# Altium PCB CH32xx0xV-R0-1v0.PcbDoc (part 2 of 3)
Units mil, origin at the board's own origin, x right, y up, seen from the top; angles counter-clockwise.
Board outline 3661.42 x 3267.72 mil, 2 copper layers (Top Layer, Bottom Layer); 68 components, 119 nets, 417 pads, 746 vias.
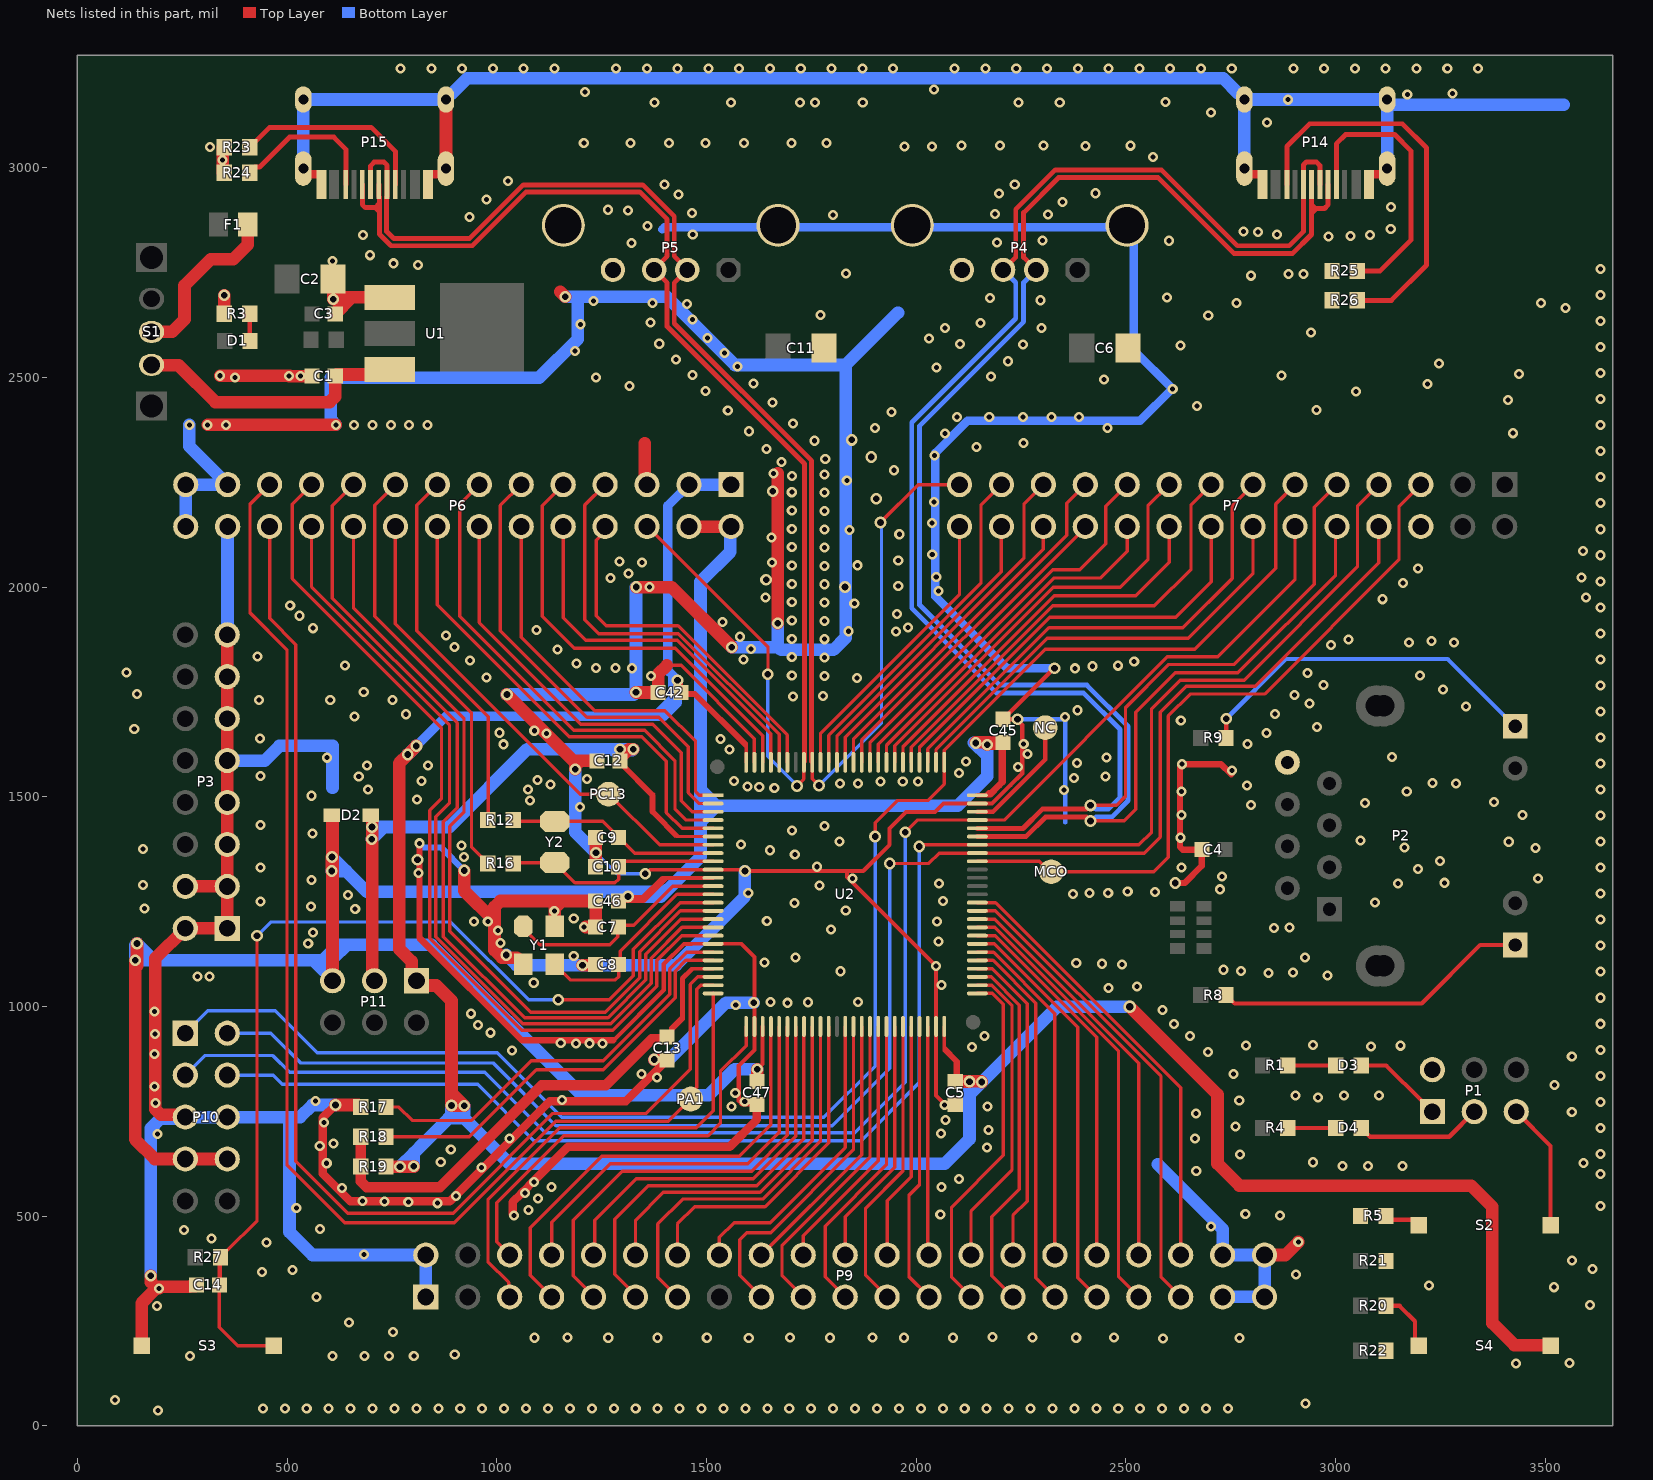
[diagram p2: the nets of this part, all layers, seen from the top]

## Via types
v1: diameter 24, hole 12, Top Layer to Bottom Layer, tented both sides, 648 vias
v2: diameter 28, hole 16, Top Layer to Bottom Layer, tented both sides, 97 vias
v3: diameter 30, hole 18, Top Layer to Bottom Layer, tented both sides, 1 vias

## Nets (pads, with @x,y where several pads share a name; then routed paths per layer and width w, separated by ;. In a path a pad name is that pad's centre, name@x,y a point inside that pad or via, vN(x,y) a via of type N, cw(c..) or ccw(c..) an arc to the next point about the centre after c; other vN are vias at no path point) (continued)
GND: C1.2 C2.2 C3.2 C4.1 C5.2 C6.2 C7.1 C8.1 C9.1 C10.1 C11.2 C12.1 C13.2 C14.1 C42.1 C45.2 C46.2 C47.1 P1.2 P2.8 P3.1 P3.2 P3.3 P3.4 P3.5 P3.7 P3.9 P3.11 P3.13 P3.15 P4.0 P4.4 P5.0 P5.4 P6.5 P6.25 P6.26 P6.27 P6.28 P7.6 P9.1 P9.2 P9.39 P9.40 P9.41 P9.42 P10.5 P10.6 P14.0 P14.A1 P14.B1 P15.0 P15.A1 P15.B1 R3.2 R5.1 R17.1 R21.2 R22.2 R23.2 R24.2 R25.2 R26.2 S3.1 U1.1 U2.10 U2.19 U2.27 U2.49 U2.74 U2.99 Y1.2 Y1.4 | length 26517
  Top Layer w8: 1364.22,1326.45 U2.10@1515.75,1326.45 1515.94,1326.26 v2@1588.24,1326.26 ; 1405.24,1813.28 1439.47,1813.28 1614.17,1638.58 U2.99@1614.17,1582.36 ; 1464.71,1149.29 U2.19@1515.75,1149.29 1583.24,1149.29
  Top Layer w10: C2.2@609.71,2734.59 611.56,2732.74 C2.2@611.56,2709.67 ; C2.2@612.21,2756.59 C2.2@614.72,2754.08 ; C3.2@614.72,2651.67 C2.2@614.72,2701.58 ; 1277.95,919.19 1398.11,1039.35 1398.11,1101.2 1446.2,1149.29 1464.71,1149.29 ; 1583.24,1149.29 1614.17,1118.36 U2.27@1614.17,952.44 1614.17,896.1 1577.04,858.97 1577.04,774.62 1585.29,766.37 C47.1@1620.21,766.37 ; v2@1588.24,1326.26 v2(1591.64,1322.86) 1834.86,1322.86 ; C5.2@2093.21,766.36 2068.86,766.36 2047.24,787.97 U2.49@2047.24,952.44 v1(2047.24,1096.4) 1834.86,1308.78 1834.86,1322.86 ; v2(2329.66,1806.6) 2328.94,1806.6 C45.2@2207.3,1684.96 v2(2241.77,1684.96) 2241.77,1682.65 2252.86,1671.56 2252.86,1637.45 2253.73,1636.57 2253.73,1626.93 2252.86,1626.05 2253.73,1625.18 2253.73,1615.53 2252.86,1614.66 2252.86,1555.73 2224.09,1526.97 2181.06,1483.93 U2.74@2145.67,1483.93 2064.97,1483.93 2045,1463.95 1975.96,1463.95 1936.47,1424.46 1936.47,1385.48 1873.85,1322.86 1834.86,1322.86
  Top Layer w15: v1@815.67,1379.21 815.67,1163.41 1059.89,919.19 1277.95,919.19 ; v2(2617.76,1294.49) 2640.39,1294.49 2681.03,1335.14 C4.1@2681.03,1374.02 ; v1@2632.22,1577.36 2628.8,1573.94 2628.8,1380.61 2635.39,1374.02 C4.1@2681.03,1374.02 ; v1(2633.76,1577.68) 2633.87,1577.79 2726.78,1577.79 v1@2751.11,1553.47 ; C4.1@2681.03,1374.36 C4.1@2681.03,1374.02
  Top Layer w20: P15.0@538.56,2998.15 538.56,2993.36 547.51,2984.41 579.86,2984.41 581.67,2982.6 P15.B1@581.67,2959.96 ; v2(615.18,765.16) 584.7,734.68 584.7,601.62 650.86,535.45 887.67,535.45 1126.57,774.35 1307.98,774.35 C13.2@1406.03,872.4 ; P15.A1@835.61,2959.96 835.61,2982.6 837.42,2984.41 869.77,2984.41 878.72,2993.36 P15.0@878.72,2998.15 ; v1@1039.94,502.38 1039.94,503.15 1037.84,505.26 1037.84,533.65 1058.53,554.34 1065.69,554.34 1066.23,554.88 v1@1066.23,556.42 ; v1@1063.41,559.23 v1@1087.61,583.43 ; v1@1087.74,583.3 1089.27,583.3 1089.81,583.84 1089.81,585.62 1169.81,665.63 1555.42,665.63 1620.21,730.42 C47.1@1620.21,766.37 ; P14.0@2782.7,2998.15 2782.7,2993.36 2791.64,2984.41 2824,2984.41 2825.81,2982.6 P14.B1@2825.81,2959.96 ; P14.A1@3079.74,2959.96 3079.74,2982.6 3081.56,2984.41 3113.91,2984.41 3122.85,2993.36 P14.0@3122.85,2998.15
  Top Layer w30: S3.1@153.21,191.36 153.21,292.44 185.42,324.65 v1@185.42,332.06 ; v2(174.88,357.77) 174.88,342.6 v1@185.42,332.06 ; v1(194.6,327.96) 189.52,327.96 v1@185.42,332.06 ; P10.5@257.21,736.36 251.47,742.1 198.44,742.1 185.26,755.28 v1(185.26,934.84) 185.26,1114.41 P3.2@257.21,1186.36 P3.1@357.21,1186.36 P3.3@357.21,1286.36 ; P3.4@257.21,1286.36 P3.3@357.21,1286.36 ; C14.1@283.44,336.36 280.44,333.36 268.56,333.36 267.26,332.06 v1@185.42,332.06 ; v1(310.42,2386.99) v1(354.11,2386.99) v1(616.26,2386.99) ; v1(340.29,2504.04) 505.7,2504.04 v1(504.86,2503.21) v1(532.28,2503.21) C1.2@559.71,2503.21 ; R24.2@346.04,2988 R23.2@346.04,3048.82 ; R3.2@350.14,2651.66 v2(350.14,2696.05) ; P3.15@357.21,1886.36 357.71,1886.36 357.21,1885.86 357.21,1786.86 357.71,1786.36 357.21,1785.86 P3.11@357.21,1686.36 P3.9@357.21,1586.36 P3.7@357.21,1486.36 P3.5@357.21,1386.36 P3.3@357.21,1286.36 ; C2.2@609.71,2734.59 609.05,2733.94 609.05,2712.18 611.56,2709.67 609.96,2708.07 v2(609.96,2686.32) ; C3.2@614.72,2651.67 653.76,2690.71 ; C2.2@614.72,2701.58 625.59,2690.71 U1.1@744.97,2690.71 U1.1@754.97,2690.71 ; v2(615.18,765.16) 670.24,765.16 670.85,764.55 671.84,764.55 675.15,761.24 R17.1@675.15,760.26 ; P15.0@878.72,2998.15 P15.0@878.72,3162.71 ; v2(922.19,1324.13) 922.19,1275.99 994.38,1203.8 ; v2@1011.96,1116.6 994.38,1134.18 994.38,1203.8 ; v2@1015.82,1116.6 1046.96,1116.6 1052.62,1110.95 1056.56,1110.95 1063.21,1104.3 Y1.2@1063.21,1100.36 ; v2(1024.15,1743.93) 1182.39,1585.69 1199.47,1585.69 ; Y1.4@1138.01,1190.91 1138.01,1233.66 1155.83,1251.48 ; 1151.69,2703.86 v2(1163.05,2692.5) ; v2(1186.92,1565.65) 1186.92,1573.14 1199.47,1585.69 ; v2(1204.2,1098.6) 1234.27,1098.6 C8.1@1235.4,1099.73 ; v1@1212.33,1189.52 1234.99,1189.52 C7.1@1235.4,1189.11 C46.2@1235.39,1251.48 1155.83,1251.48 ; C10.1@1235.4,1333.23 C9.1@1235.4,1402.61 ; C12.1@1238.69,1585.69 1199.47,1585.69 ; v2(1331.85,1749.37) 1332.53,1748.68 C42.1@1384.49,1748.68 1384.49,1792.53 1405.24,1813.28 ; v2(1332.61,2000.18) 1416.87,2000.18 v2(1560.42,1856.63) ; 1352.52,2343.09 1352.52,2250.04 P6.5@1358.21,2244.36 ; v2(1375.46,873.41) 1403.46,873.41 1404.24,874.19 C13.2@1406.03,872.4 ; v2(1669.62,1913.93) v1@1669.62,2270.87 ; P9.42@2830.71,407.44 2880.08,407.44 v1(2911.05,438.41) ; 994.38,1203.8 994.38,1237.5 1008.37,1251.48 1155.83,1251.48
  Bottom Layer w8: v2(1236.3,1366.46) 1286.52,1316.25 v2(1354.01,1316.25)
  Bottom Layer w10: v2(2241.77,1684.96) 2355.18,1684.96 2355.18,1438.4
  Bottom Layer w15: v1@815.67,1379.21 867.11,1379.21 v2(922.19,1324.13)
  Bottom Layer w20: 1394.51,2852.66 1399.51,2857.66 2502.7,2857.66 2518.46,2841.9 2518.46,2565.52 v1(2611.69,2472.29) ; v2(2329.66,1806.6) 2216.8,1806.6 2045.84,1977.55 2045.84,2320.25 2122.33,2396.74 2533.85,2396.74 v1@2610.92,2473.81
  Bottom Layer w30: v2(174.88,357.77) 174.88,709.7 197.21,732.03 252.88,732.03 P10.5@257.21,736.36 P10.6@357.21,736.36 505.67,736.36 ; P6.28@258.21,2144.36 P6.27@258.21,2244.36 P6.25@358.21,2244.36 266.34,2336.23 v1@266.34,2386.59 ; P3.9@357.21,1586.36 446.8,1586.36 481.8,1621.36 608.21,1621.36 608.21,1521.36 ; P3.15@357.21,1886.36 357.71,1886.86 357.71,2143.86 P6.26@358.21,2144.36 ; P15.0@538.56,2998.15 P15.0@538.56,3162.71 P15.0@878.72,3162.71 878.72,3171.99 883.05,3176.32 892.32,3176.32 929.72,3213.71 2731.7,3213.71 2769.09,3176.32 2778.37,3176.32 2782.7,3171.99 P14.0@2782.7,3162.71 ; v2(615.18,765.16) 560.03,765.16 531.22,736.36 505.67,736.36 ; v1(616.26,2386.99) 604,2399.24 604,2499.25 1100.67,2499.25 1193.06,2591.65 1193.06,2692.5 ; P9.1@830.71,307.44 P9.2@830.71,407.44 560.54,407.44 505.67,462.31 505.67,736.36 ; v2(1022.37,1122.92) 1046.69,1098.6 v2(1204.2,1098.6) 1427.65,1098.6 1591.64,1262.59 v2(1591.64,1322.86) ; v2(1024.15,1743.93) 1326.41,1743.93 v2(1331.85,1749.37) 1331.85,1999.41 v2(1332.61,2000.18) ; v2(1163.05,2692.5) 1193.06,2692.5 ; v2(1186.92,1565.65) 1186.92,1415.84 v2(1236.3,1366.46) ; v2(1375.46,873.41) 1410.99,873.41 1546.82,1009.23 v2(1612.92,1009.23) ; v2(1560.42,1856.63) 1671.57,1856.63 ; v2(1669.62,1913.93) 1669.62,1858.58 1671.57,1856.63 ; 1956.65,2654.66 1831.65,2529.66 ; 2576.15,623.54 2730.71,468.98 P9.40@2730.71,407.44 P9.42@2830.71,407.44 P9.41@2830.71,307.44 P9.39@2730.71,307.44 ; P14.0@2782.7,2998.15 P14.0@2782.7,3162.71 ; P14.0@3122.85,2998.15 P14.0@3122.85,3154.52 ; 3544.32,3150.19 3127.18,3150.19 P14.0@3122.85,3154.52 ; 1193.06,2692.5 1405.12,2692.5 1567.96,2529.66 1831.65,2529.66 ; 1671.57,1856.63 1677.92,1850.28 1802.63,1850.28 1831.65,1879.31 1831.65,2529.66 ; P14.0@2782.7,3162.71 P14.0@3122.85,3162.71 P14.0@3122.85,3154.52
  other v1: 191.6,36.82 442.13,41.5 494.43,41.5 546.73,41.5 599.03,41.5 651.32,41.5 703.62,41.5 755.92,41.5 808.22,41.5 860.52,41.5 912.82,41.5 965.12,41.5 1017.42,41.5 1069.72,41.5 1122.02,41.5 1174.32,41.5 1226.62,41.5 1278.92,41.5 1331.22,41.5 1383.52,41.5 1435.82,41.5 1488.12,41.5 1540.41,41.5 1592.71,41.5 1645.01,41.5 1697.31,41.5 1749.61,41.5 1801.91,41.5 1854.21,41.5 1906.51,41.5 1958.81,41.5 2011.11,41.5 2063.41,41.5 2115.71,41.5 2168.01,41.5 2220.31,41.5 2272.61,41.5 2324.91,41.5 2377.2,41.5 2429.5,41.5 2481.8,41.5 2534.1,41.5 2586.4,41.5 2638.7,41.5 2691,41.5 2743.3,41.5 2928.04,53.07 89.88,61.94 3429.78,148.85 3557.96,150.13 268.2,166.17 607.92,166.19 684.5,166.19 743.23,166.19 801.96,166.19 899.65,170.11 2588.78,208.08 1600.73,209.45 1089.54,210.13 1265.72,210.13 1383.18,210.13 1500.64,210.13 1699,210.78 1794.28,210.13 1895.54,210.78 1970.47,210.13 2087.93,210.13 2277.32,210.78 2381.57,210.13 2471.19,210.38 2771.38,209.92 1168.06,211.08 2182.38,212.1 752.38,224.25 647.76,246.19 189.7,285.56 3606.24,288.27 569.59,307.27 3520.68,330.63 3223.25,334.54 2905.17,361.29 440.25,367.1 512.58,371.6 3612.17,373.83 3563.88,394.17 683.72,408.85 450.3,437.43 319.53,446.87 253.81,466.97 578.08,469.44 2702.61,475.08 1040.71,501.3 2866.99,501.86 2057.41,503.6 2784.69,505.73 1075.69,514.87 521.78,519.31 3631.78,524.36 858.07,530.93 788.86,534.31 732.37,535.46 679.94,536.29 1098.59,542.55 902.67,548.33 1067.54,555.11 631.09,567.58 1130.56,569.74 2060.52,569.58 1089.04,581.99 2101.61,588.26 3631.78,600.23 2667.79,607.47 963.7,615.95 3016.4,619.76 3077.38,619.76 3159.75,619.76 594.4,626.24 3590.8,626.6 866.3,628.83 2946.2,628.64 2771.99,647.61 3631.78,648.49 890.21,659.37 2169.21,664.16 577.74,667.52 610.31,673.2 1030.74,685.31 2665.22,685.19 190.41,695.82 2059.15,697.65 2172.9,705.71 3631.78,710.55 2761.74,714.23 587.59,723.58 2069.8,729.59 2666.93,744.98 3563.19,748.55 1559.88,761.34 2169.67,761.57 2067.96,765.62 186.55,769.53 3631.78,772.62 1591.16,773.5 567.89,775.08 2770.28,775.73 1155.56,776.94 2957.91,782.59 2904.06,787.34 3103.63,787.34 3020.36,788.18 1568.53,793.49 183.66,809.03 3521.77,812.99 1382.05,830.54 3631.78,834.68 1345.34,839.54 2756.69,839.13 3563.19,880.87 183.74,886.43 2695.7,891.01 1036.03,895.07 3631.78,896.75 2133.52,902.97 3084.41,904.13 2786.56,906.72 3154.31,906.48 2945.84,908.01 1188.43,911.55 1252.38,911.55 1152.46,912.55 1220.65,912.3 2652.95,929.56 2162.45,930.01 985.13,937.47 954.96,955.46 2615.09,958.3 3631.78,958.81 938.61,982.77 183.3,987.76 2587.76,991.24 1569.73,1003.61 1693.2,1008.89 1741.54,1010.11 1652.18,1010.92 1860.98,1011.06 3631.78,1020.88 2458.12,1043.87 2526.14,1048.12 2060.66,1051.18 1088.08,1056.6 286.03,1071.34 314.43,1071.34 2980.38,1074.13 2840.2,1080.37 2898.9,1081.19 3631.78,1082.94 1819.45,1084.05 2774.17,1084.71 2732.3,1087.67 2490.71,1099.85 2443.24,1101.97 2381.6,1103.39 1638.14,1104.81 1712.36,1116.58 2927.41,1116.36 1183.44,1120.75 3631.78,1145 550.31,1150.17 1008.72,1151.66 2053.44,1155.11 561.8,1176.18 1003.1,1181.08 1796.64,1183.62 2853.68,1187 2890.63,1187.87 1207.4,1189.11 945.13,1202.27 2049.83,1202.74 978.44,1203.14 1643.7,1204.1 3631.78,1207.07 1183.44,1210.05 1137.01,1227.48 1831.98,1229.08 662.36,1232.84 159.59,1233.75 557.4,1237.99 1709.93,1246.75 3094.19,1248.26 436.16,1250.21 2063.54,1251.09 645.12,1265.53 2374.19,1268.2 3631.78,1269.13 1599.51,1270.38 2457.87,1270.71 2413.46,1270.94 2569.16,1272.79 2504.4,1274.67 2724.73,1279.51 1769.54,1288.64 156.18,1289.6 2054.16,1293.68 3148.33,1293.79 3259.69,1295.02 558.37,1301.49 1848.36,1305.25 3482.39,1305.28 2729.42,1310.23 812.88,1318.31 3196.69,1328.34 436.16,1331.67 2632.82,1331.21 3631.78,1331.2 1763.45,1333.21 3249.23,1346.7 921.99,1356.03 1710.47,1362.67 1651.74,1372.59 155.91,1375.99 3477.17,1378.33 3164.4,1379.3 915.38,1383.82 1582.01,1386.15 815.67,1389.21 3412.89,1392.84 1817.57,1393.49 3631.78,1393.26 3059.48,1396.25 2630.67,1402.45 560.24,1412.22 1704.04,1419.73 1781.52,1430.7 436.16,1432.49 3631.78,1455.32 3445.86,1456.6 2632.08,1456.87 1198.69,1476.21 2797.87,1480.91 3070.08,1485.27 3377.55,1487.43 1079.51,1490.71 810.12,1493.85 558,1502.57 2633.03,1512.23 3169.7,1512.83 2352.6,1516.24 693.14,1517.5 1074.07,1516.99 3631.78,1517.39 1661.58,1521.45 1625.79,1523.67 1597.73,1524.11 2788.76,1527.04 1128,1529.68 1861.36,1531.23 1818.03,1532.25 3287.33,1531.9 3231.21,1533.2 1914.55,1536.36 1967.9,1536.36 2004.51,1536.36 1565.36,1537.46 819.89,1538.08 1096.73,1540.1 1215.41,1542.81 2376.71,1544.93 670.8,1548.46 2450.88,1548.51 436.16,1549.55 2101.58,1556.49 2752.95,1562.67 2242.32,1571.08 690.69,1574.76 835.83,1574.6 3631.78,1579.45 2383.22,1580.13 2118.89,1584.5 594.92,1593.21 2453.43,1593.58 3134.73,1594.43 2264.98,1602.09 1554.56,1612.67 1015.77,1625.26 2256.41,1626.05 2790.41,1626.37 1533.76,1637.6 434.97,1639.49 3631.78,1641.52 1118.89,1650.59 1006.09,1652.78 2835.75,1652.32 1089.29,1657.55 135.45,1661.76 2955.65,1666.03 2630.88,1681.54 2355.18,1690.68 660.43,1691.46 783.45,1696.86 2855.76,1697.36 3631.78,1703.58 2384.12,1706.38 3311.35,1715.83 2937.33,1722.19 433.34,1730.68 602.82,1730.66 751.08,1731.25 1706.45,1738.7 1777.36,1740.63 2902.45,1742.28 141.54,1745.31 682.7,1750.42 3256.09,1756.29 3631.78,1765.64 2971.02,1767.11 1859.2,1783.64 975.01,1784.57 1367.66,1787.82 1780.94,1788.36 3201.33,1788.86 1703.32,1789.34 2933.19,1794.89 116.64,1796.56 1322.78,1806.58 2379.11,1806.49 1236.04,1807.15 1283.46,1807.15 2420.78,1811.35 2481.46,1812.56 637.73,1813.42 1189.77,1817.56 2519.89,1823.08 936.11,1824.63 1588.44,1827.6 3631.78,1827.71 1780.94,1832.05 1703.32,1833.04 429.43,1835.09 1144.27,1851.74 1605.68,1852.01 898.95,1857.15 2989.59,1861.54 3282.71,1867.52 3175.08,1868.24 3228.53,1871.13 1780.94,1875.74 3030.51,1875.18 1703.32,1876.73 1579.34,1881.7 878.63,1884.44 3631.78,1889.77 1838.68,1894.74 1951.85,1894.55 1094.71,1897.33 561.82,1902 1980.19,1903.96 1537.69,1916.65 1780.94,1919.44 1703.32,1920.42 529.71,1931.7 1954.06,1935.7 3631.78,1951.84 507.38,1956.39 1852.32,1961.15 1780.94,1963.13 1703.32,1964.11 3112.33,1971.12 1640.74,1975.45 3596.78,1974.93 2053.09,1991.2 1363.69,2000.75 1957.17,2002.27 1780.94,2006.82 1703.32,2007.8 3160.54,2009.6 3631.78,2013.9 1270.96,2021.41 2047.84,2023.64 3586.53,2023.19 1314.37,2032.85 3196.58,2044.66 1780.94,2050.51 1703.32,2051.49 1859.85,2052.08 1655.66,2058.22 1345.94,2058.89 1292.27,2061.26 1957.17,2063.87 3631.78,2075.96 2038.27,2077.79 3590.15,2085.93 1780.94,2094.2 1703.32,2095.19 1654.6,2118.22 1959.66,2126.09 1841.14,2135.83 1780.94,2137.89 3631.78,2138.03 1703.32,2138.88 2037.58,2153.23 1780.94,2181.59 1703.32,2182.57 3631.78,2200.09 2042.38,2203.29 1780.94,2225.28 1703.32,2226.26 1834.47,2254.04 3631.78,2262.16 1703.8,2264.95 1780.94,2268.97 1659.87,2270.87 1946.73,2278.68 1679.23,2298.32 1783.16,2305.56 2044.04,2314.11 3631.78,2324.22 1642.91,2329.76 2143.83,2334.55 2255.47,2343.57 1757.61,2349 2068.99,2366.11 3422.65,2366.96 1601,2371.67 1901.4,2378.97 2456.31,2379.13 3631.78,2386.29 266.73,2386.99 659.95,2386.99 703.64,2386.99 747.33,2386.99 791.03,2386.99 834.72,2386.99 1706.5,2389.89 2097.23,2405.76 2174.15,2405.76 2254.35,2405.76 2323.08,2405.76 2387.73,2405.76 1940.79,2417.32 1550.71,2421.26 2954.33,2421.86 2670.05,2431.96 1657.19,2440.37 3411.39,2445.76 3631.78,2448.35 3048.92,2466.02 1497.62,2468.06 1316.73,2479.4 3219.2,2483.99 1611.57,2485.59 2447.46,2494.95 375.87,2499.78 1236.7,2499.87 2178.87,2502.27 2871.5,2504.43 1466.89,2505.78 3437.28,2507.67 3631.78,2510.41 2048,2524.09 1573.45,2526.2 3247.04,2533.56 2218.7,2538.63 1427.54,2543.09 1542.72,2558.44 1186.69,2562.89 3631.78,2572.48 2630.44,2575.94 2254.19,2578.45 2104.1,2579.33 1387.28,2580.32 2030.88,2592.48 1502.7,2594.46 2940.98,2607.32 2069.14,2618.29 2298.34,2618.27 1199.9,2626.74 2153.3,2630.25 1366.94,2631.39 3631.78,2634.54 1466.34,2637.79 1771.55,2648.55 2696.39,2648.02 3548.2,2665.51 1453.28,2675.49 1371.01,2677.04 2763.87,2677.16 3489.38,2677.15 1230.72,2681.78 2296.61,2684.06 2175.74,2689.8 2598.24,2690.96 3631.78,2696.61 2798.27,2742.5 1833.07,2747.49 2887.24,2746.86 2923.15,2747.09 3631.78,2758.67 812.45,2768.2 754.07,2772.2 608.21,2777.59 698.09,2791.39 1320.63,2820.51 2193.07,2821.72 2301.5,2826.65 2602.84,2825.92 2983.58,2836.04 3035.83,2837.6 681.3,2839.37 3082.38,2839.67 1467.16,2840.68 2860.41,2840.72 2815.04,2846.77 2779.95,2847.98 3131.52,2854.15 1358.94,2860.84 935.29,2882.99 1801.11,2887.1 2313.82,2888.26 2188.14,2889.9 1465.81,2891.76 1312.56,2897.81 1264.84,2899.83 3132.55,2906.91 2349.15,2918.65 975.83,2923.98 1433.55,2936.12 2197.18,2938.37 2427.19,2939.19 1399.94,2959.65 2234.96,2959.73 1026.17,2968.09 346.04,3018.41 2565.08,3025.24 316.42,3049.42 1971.85,3051.05 2037.48,3051.05 2403.41,3051.61 2108.37,3052.8 2200.27,3052.8 2303.54,3052.8 2511.48,3052.48 1207.35,3058.85 1319.05,3058.85 1410.8,3058.85 1497.9,3058.85 1589.55,3058.85 1702.62,3058.85 1786.25,3058.85 2836.88,3108.26 2702.86,3131.89 1375.5,3155.42 1558.35,3155.42 1723.23,3155.42 1758.19,3155.42 1872.57,3155.42 2243.94,3155.42 2342.3,3155.42 2594.75,3157.08 2886.33,3162.21 3170.96,3174.28 3279.3,3176.67 1210.2,3180.77 2042.01,3186.96 770.41,3236.57 843.82,3236.57 917.23,3236.57 990.63,3236.57 1064.04,3236.57 1137.45,3236.57 1284.27,3236.57 1357.68,3236.57 1431.09,3236.57 1504.5,3236.57 1577.91,3236.57 1651.32,3236.57 1724.73,3236.57 1798.14,3236.57 1871.55,3236.57 1944.95,3236.57 2091.77,3236.57 2165.18,3236.57 2238.59,3236.57 2312,3236.57 2385.41,3236.57 2458.82,3236.57 2532.23,3236.57 2605.64,3236.57 2679.05,3236.57 2752.46,3236.57 2899.27,3236.57 2972.68,3236.57 3046.09,3236.57 3119.5,3236.57 3192.91,3236.57 3266.32,3236.57 3339.73,3236.57
  other v2: 810.67,1350.21 1830.1,2000.28 1642.14,2017.8 1904.85,2211.01 1658.22,2228.32 1892.87,2310.07 1846.2,2351.07
KEY: P1.5 S2.1 | length 304.5
  Top Layer w10: P1.5@3430.77,749.27 3512.71,667.33 S2.1@3512.71,478.75
LED1: D3.2 P1.1 | length 215.5
  Top Layer w10: D3.2@3060.84,859.36 3120.68,859.36 3205.77,774.27 P1.1@3230.77,749.27
LED2: D4.2 P1.3 | length 303.4
  Top Layer w10: D4.2@3060.84,710.36 3066.73,704.47 3081.73,689.47 3270.96,689.47 P1.3@3330.77,749.27
MCO: MCO.1 P7.5 U2.67 | length 1721.9
  Top Layer w8: U2.67@2145.67,1346.14 2293.92,1346.14 2318.7,1321.36 MCO.1@2322.21,1321.36 2566.74,1321.36 2600.91,1355.53 2600.91,1692.79 2653.19,1745.07 2830.6,1745.07 3151.06,2065.52 3151.06,2192.21 P7.5@3203.21,2244.36
NC: NC.1 U2.73 | length 289.7
  Top Layer w10: U2.73@2145.67,1464.25 2183.05,1464.25 2307.69,1588.88 NC.1@2307.69,1664.95
NetC1_1: C1.1 S1.2 U1.3 | length 670.4
  Top Layer w30: S1.2@177.31,2530.61 179.28,2528.64 241.52,2528.64 329.13,2441.02 601.53,2441.02 614.71,2454.2 C1.1@614.71,2503.21 ; C1.1@618.45,2506.95 743.21,2506.95 U1.3@754.97,2518.71
NetD1_2: D1.2 R3.1 | length 65
  Top Layer w10: R3.1@410.77,2651.66 410.77,2587.61 D1.2@411.46,2586.93
NetD3_1: D3.1 R1.2 | length 111.1
  Top Layer w10: R1.2@2886.21,859.36 2995.95,859.36 D3.1@2996.93,860.34
NetD4_1: D4.1 R4.2 | length 112.5
  Top Layer w10: R4.2@2886.21,710.36 2996.68,710.36 D4.1@2998.15,711.82
NetF1_2: F1.2 S1.1 | length 410.2
  Top Layer w30: S1.1@177.31,2609.35 226.23,2609.35 255.27,2638.39 255.27,2719.3 317.98,2782.01 371.72,2782.01 406.25,2816.54 F1.2@406.25,2864.6
NetP2_9: P2.9 R8.2 | length 756.3
  Top Layer w10: R8.2@2738.84,1027.36 2738.84,1026.37 2752.15,1013.07 2753.13,1013.07 2759.39,1006.81 3205.36,1006.81 3344.83,1146.28 3428.13,1146.28 P2.9@3428.21,1146.36
NetP2_12: P2.12 R9.2 | length 860.6
  Top Layer w10: R9.2@2738.84,1640.36 2739.31,1640.83 v2(2739.31,1686)
  Bottom Layer w10: v2(2739.31,1686) 2882.21,1828.9 3267.32,1828.9 P2.12@3428.21,1668.01
NetP14_A5: P14.A5 R25.1 | length 670.9
  Top Layer w11.8: P14.A5@3001.99,2959.96 3001.99,3057.06 3024.06,3079.14 3140.98,3079.14 3179.6,3040.52 3179.6,2827.45 3106.21,2754.06 R25.1@3051.97,2754.06
NetP14_B5: P14.B5 R26.1 | length 949
  Top Layer w11.8: P14.B5@2883.88,2959.96 2883.88,3050.78 2938.02,3104.92 3159.1,3104.92 3216.7,3047.32 3216.7,2767.57 3133.03,2683.9 R26.1@3051.97,2683.9
NetP15_A5: P15.A5 R23.1 | length 469.6
  Top Layer w11.8: R23.1@410.77,3048.82 458.43,3096.48 700.59,3096.48 758.16,3038.91 P15.A5@758.16,2960.27
NetP15_B5: P15.B5 R24.1 | length 360.8
  Top Layer w11.8: R24.1@410.77,2988 410.77,2988.94 423.18,3001.35 434.01,3001.35 505.55,3072.89 611.26,3072.89 640.05,3044.1 P15.B5@640.05,2960.27
NetR5_2: R5.2 S2.2 | length 86.7
  Top Layer w10: R5.2@3120.1,500.58 3129.37,491.32 3185.19,491.32 S2.2@3197.75,478.75
NetR20_2: R20.2 S4.2 | length 146.3
  Top Layer w10: R20.2@3120.1,286.28 3152.88,286.28 3189.73,249.43 3189.73,199.38 S4.2@3197.75,191.36
NRST: C14.2 R27.1 S3.2 U2.14 | length 2493.5
  Top Layer w8: C14.2@338.44,339.41 338.44,400.24 355.56,417.35 356.54,417.35 428.23,489.04 v2(428.23,1168.52) ; C14.2@341.25,339.41 R27.1@341.25,402.06 ; C14.2@341.37,339.29 338.2,336.11 338.2,235.13 381.97,191.36 S3.2@468.17,191.36 ; v2(1146.21,1016.36) 1268.32,1016.36 1325.22,1073.27 1325.22,1136.13 1436.81,1247.71 U2.14@1515.75,1247.71
  Bottom Layer w8: v2(428.23,1168.52) 461.05,1201.34 890.69,1201.34 1075.67,1016.36 v2(1146.21,1016.36)
PA0: P6.24 U2.23 | length 2937.4
  Top Layer w8: P6.24@458.21,2144.36 458.21,1925.41 520.69,1862.93 520.69,631.1 644.51,507.28 896.02,507.28 1133.65,744.91 1356.33,744.91 1461.51,850.1 1461.51,1052.59 1479.47,1070.55 U2.23@1515.75,1070.55
PA1: P6.23 PA1.1 U2.24 | length 3133.9
  Top Layer w8: P6.23@458.21,2244.36 411.46,2197.61 411.46,1938.62 499.57,1850.51 499.57,622.9 637.74,484.73 898.26,484.73 1140.09,726.56 1409.33,726.56 PA1.1@1464.81,782.03 ; PA1.1@1462.18,779.41 1462.18,793.22 1476.75,807.79 1476.75,1041.35 1486.27,1050.86 U2.24@1515.75,1050.86
PA2: P9.5 U2.25 | length 1158.1
  Top Layer w8: P9.5@1030.71,307.44 1028.13,310.02 1028.13,341.92 978.84,391.21 978.84,539.44 1150.04,710.65 1475.14,710.65 1515.75,751.26 U2.25@1515.75,1031.18
PA3: P9.6 U2.26 | length 1006.3
  Top Layer w8: P9.6@1030.71,407.44 999.41,438.74 999.41,532.39 1159.07,692.05 1503.6,692.05 1533.2,721.65 1533.2,845.19 1594.49,906.48 U2.26@1594.49,952.44
PA4: P9.7 U2.29 | length 1096.5
  Top Layer w8: P9.7@1130.71,307.44 1079.47,358.68 1079.47,472.38 1249.98,642.89 1578.54,642.89 1653.54,717.9 U2.29@1653.54,952.44
PA5: P9.8 U2.30 | length 962.1
  Top Layer w8: P9.8@1130.71,407.44 1130.71,485.45 1270.22,624.95 1598.55,624.95 1673.23,699.63 U2.30@1673.23,952.44
PA6: P9.9 U2.31 | length 1057.6
  Top Layer w8: P9.9@1230.71,307.44 1230.71,309.63 1182.08,358.26 1182.08,490.54 1298.83,607.29 1607.59,607.29 1692.91,692.61 U2.31@1692.91,952.44
PA7: P9.10 U2.32 | length 908.4
  Top Layer w8: P9.10@1230.71,407.44 1233.28,410.01 1233.28,490.69 1331.94,589.35 1611.53,589.35 1712.6,690.42 U2.32@1712.6,952.44
PA9: P7.8 P10.2 U2.68 | length 3940
  Top Layer w8: v2(1936.96,1341.09) 2029.87,1341.09 2054.6,1365.82 U2.68@2145.67,1365.82 2543.46,1365.82 2581.64,1404 2581.64,1701.92 2643.45,1763.73 2808.86,1763.73 3103.21,2058.08 P7.8@3103.21,2144.36
  Bottom Layer w8: P10.2@357.21,936.36 461.11,936.36 532.21,865.26 991.72,865.26 1141.06,715.93 1799.91,715.93 1936.96,852.98 v2(1936.96,1341.09)
PA10: P7.7 P10.4 U2.69 | length 4045.8
  Top Layer w8: v2(2007.19,1381.59) 2012.6,1381.59 2016.52,1385.51 U2.69@2145.67,1385.51 2531.13,1385.51 2561.18,1415.55 2561.18,1709.91 2629.34,1778.07 2782.17,1778.07 3052.1,2048 3052.1,2193.25 P7.7@3103.21,2244.36
  Bottom Layer w8: P10.4@357.21,836.36 466.75,836.36 488.73,814.38 954.32,814.38 1088.49,680.21 1868.6,680.21 2007.19,818.8 v2(2007.19,1381.59)
PA11: P4.2 P7.10 P14.A7 P14.B7 U2.70 | length 4394
  Top Layer w8: v2(2415.37,1442.54) 2495.73,1442.54 2523.11,1469.92 2523.11,1701.57 2617.15,1795.61 2767.27,1795.61 2999.88,2028.22 2999.88,2141.03 P7.10@3003.21,2144.36
  Top Layer w11.8: U2.70@2145.67,1405.19 2146.11,1405.64 2262.42,1405.64 2308.42,1451.64 2360.46,1451.64 2406.27,1451.64 v2(2415.37,1442.54) ; P4.2@2286.16,2756.36 2256.19,2786.33 2256.19,2893.08 2339.45,2976.34 2576.93,2976.34 2758.13,2795.14 2896.95,2795.14 2942.49,2840.68 2942.49,2891.63 ; P14.A7@2942.93,2959.96 2942.93,2931.42 2942.49,2930.97 2942.49,2911.61 ; P14.B7@2982.3,2959.96 2982.3,2911.75 2973.51,2902.95 2953.81,2902.95 ; 2942.49,2891.63 2942.49,2902.95 ; 2942.49,2891.63 2953.81,2902.95 ; 2942.49,2902.95 2951.15,2902.95 ; 2942.49,2902.95 2942.49,2911.61 ; 2942.49,2911.61 2951.15,2902.95 ; 2951.15,2902.95 2953.81,2902.95
  Bottom Layer w11.8: P4.2@2286.16,2756.36 2256.19,2726.39 2256.19,2632.76 2008.19,2384.75 2008.19,1957.47 2199.52,1766.14 2407.03,1766.14 2505.01,1668.15 2505.01,1490.68 2465.97,1451.64 2428.65,1451.64 2419.55,1442.54 v2(2415.37,1442.54)
PA12: P4.3 P7.9 P14.A6 P14.B6 U2.71 | length 4437.1
  Top Layer w8: v2(2415.37,1479.54) 2477.67,1479.54 2499.08,1500.94 2499.08,1712.43 2602.2,1815.55 2758.6,1815.55 2949.56,2006.51 2949.56,2190.71 P7.9@3003.21,2244.36
  Top Layer w11.8: U2.71@2145.67,1424.88 2146.11,1424.44 2254.63,1424.44 2300.63,1470.44 2393.52,1470.44 2406.27,1470.44 v2(2415.37,1479.54) ; P4.3@2207.42,2756.36 2237.39,2786.33 2237.39,2900.87 2331.66,2995.14 2584.72,2995.14 2765.92,2813.94 2889.16,2813.94 2923.69,2848.47 2923.69,2903.82 2923.69,2930.97 2923.25,2931.42 P14.B6@2923.25,2959.96 2923.25,3006.46 2930.74,3013.96 2954.17,3013.96 2962.62,3005.52 P14.A6@2962.62,2959.96
  Bottom Layer w11.8: P4.3@2207.42,2756.36 2237.39,2726.39 2237.39,2640.54 1989.39,2392.54 1989.39,1949.68 2191.74,1747.34 2399.24,1747.34 2486.21,1660.36 2486.21,1498.47 2458.18,1470.44 2428.65,1470.44 2419.55,1479.54 v2(2415.37,1479.54)
PA13: P7.12 P10.3 U2.72 | length 3763.7
  Top Layer w8: v2(1973.71,1415.58) 2002.69,1444.56 U2.72@2145.67,1444.56 2209.81,1444.56 2599.01,1833.76 2719.34,1833.76 2903.21,2017.63 P7.12@2903.21,2144.36
  Bottom Layer w8: P10.3@257.21,836.36 303.85,883 466.32,883 506.19,843.13 971.45,843.13 1115.61,698.97 1853.17,698.97 1973.71,819.51 v2(1973.71,1415.58)
PA14: P7.11 P10.1 U2.76 | length 3875.4
  Top Layer w8: v2(1902.03,1405.61) 1902.03,1438.61 1954.47,1491.05 2027.53,1491.05 2066.93,1530.45 2066.93,1611.44 2307.71,1852.22 2664.34,1852.22 2857.04,2044.92 2857.04,2198.19 P7.11@2903.21,2244.36
  Bottom Layer w8: P10.1@257.21,936.36 310.43,989.58 471.32,989.58 571.34,889.56 1000.79,889.56 1154.57,735.79 1779.91,735.79 1902.03,857.91 v2(1902.03,1405.61)
PA15: P7.14 U2.77 | length 1072
  Top Layer w8: U2.77@2047.24,1582.36 2047.24,1612.97 2312.49,1878.21 2648.5,1878.21 2803.21,2032.92 P7.14@2803.21,2144.36
PB0: P9.13 U2.35 | length 937.3
  Top Layer w8: P9.13@1430.71,307.44 1383.41,354.74 1383.41,481.48 1442.8,540.87 1633.74,540.87 1771.65,678.78 U2.35@1771.65,952.44
PB1: P9.14 U2.36 | length 792.5
  Top Layer w8: P9.14@1430.71,407.44 1430.71,481.4 1472.07,522.76 1639.49,522.76 1791.34,674.61 U2.36@1791.34,952.44
PB3: P7.26 U2.89 | length 724.4
  Top Layer w8: U2.89@1811.02,1582.36 1811.02,1644.47 2203.21,2036.65 P7.26@2203.21,2144.36
PB4: P7.25 U2.90 | length 832.6
  Top Layer w8: U2.90@1791.34,1582.36 1791.34,1646.24 2154.49,2009.39 2154.49,2195.64 P7.25@2203.21,2244.36
PB5: P7.28 U2.91 | length 699.3
  Top Layer w8: U2.91@1771.65,1582.36 1771.65,1649.97 2103.21,1981.53 P7.28@2103.21,2144.36
PB6: P5.2 P7.27 P15.A7 P15.B7 U2.92 | length 3465.9
  Top Layer w8: U2.92@1751.97,1582.36 1751.97,1543.14 1767.98,1527.13 v2(1767.98,1526.78) ; v2(1914.85,2154.08) 2005.13,2244.36 P7.27@2103.21,2244.36
  Top Layer w11.8: P15.A7@699.11,2960.27 699.11,3004.8 707.62,3013.32 731,3013.32 738.48,3005.84 738.48,2931.72 737.03,2930.28 737.03,2911.92 737.03,2895.21 737.03,2848.49 754.75,2830.77 934.6,2830.77 1063.04,2959.22 1347.78,2959.22 1423.03,2883.97 1423.03,2789.38 1454,2758.41 P5.2@1454,2756.36 1423.03,2725.39 1423.03,2628.44 1750.53,2300.94 1750.53,1604.3 1750.57,1604.26 U2.92@1750.57,1583.76
  Bottom Layer w8: v2(1767.98,1526.78) 1917.3,1676.09 1917.3,2151.62 v2(1914.85,2154.08)
PB7: P5.3 P6.6 P15.A6 P15.B6 U2.93 | length 3307.8
  Top Layer w8: P6.6@1358.21,2144.36 1359.63,2144.36 1646.5,1857.49 v2@1646.5,1786.36 ; v2(1716,1526) 1716,1526.06 1732.28,1542.34 U2.93@1732.28,1582.36
  Top Layer w11.8: P15.B6@679.42,2960.27 679.42,2912 686.46,2904.96 710.49,2904.96 ; P15.A6@718.79,2960.27 718.79,2931.72 720.23,2930.28 720.23,2914.71 ; U2.93@1733.68,1583.76 1733.68,1604.26 1733.73,1604.3 1733.73,2293.98 1406.23,2621.48 1406.23,2725.39 P5.3@1375.26,2756.36 1375.26,2758.41 1406.23,2789.38 1406.23,2877.01 1340.82,2942.42 1070,2942.42 941.56,2813.97 747.79,2813.97 720.23,2841.53 720.23,2895.21 ; 710.49,2904.96 720.23,2914.71 ; 710.49,2904.96 720.23,2904.96 ; 710.49,2904.96 720.23,2895.21 ; 720.23,2895.21 720.23,2904.96 ; 720.23,2904.96 720.23,2914.71
  Bottom Layer w8: v2(1645.8,1792.18) 1645.8,1596.2 v2(1716,1526)
PB8: P6.8 U2.95 | length 859.9
  Top Layer w8: P6.8@1258.21,2144.36 1258.21,2132.3 1237.37,2111.46 1237.37,1931.36 1260.43,1908.3 1432.08,1908.3 1692.91,1647.46 U2.95@1692.91,1582.36
PB9: P6.7 U2.96 | length 985.7
  Top Layer w8: P6.7@1258.21,2244.36 1209.67,2195.82 1209.67,1921.82 1242.57,1888.92 1433.07,1888.92 1673.23,1648.76 U2.96@1673.23,1582.36
PB10: P9.25 U2.47 | length 675.2
  Top Layer w8: U2.47@2007.87,952.44 2007.87,575.09 1982.83,550.04 1982.83,355.32 P9.25@2030.71,307.44
PB11: P9.26 U2.48 | length 546.3
  Top Layer w8: U2.48@2027.56,952.44 2027.75,952.25 2027.75,410.4 P9.26@2030.71,407.44
PB12: P9.27 U2.51 | length 840.6
  Top Layer w8: P9.27@2130.71,307.44 2084.31,353.84 2084.31,521.62 2207.53,644.83 2207.53,1005.09 2181.44,1031.18 U2.51@2145.67,1031.18
PB13: P9.28 U2.52 | length 738.3
  Top Layer w8: P9.28@2130.71,407.44 2130.71,512.49 2228.3,610.08 2228.3,1002.7 2180.14,1050.86 U2.52@2145.67,1050.86
PB14: P9.29 U2.53 | length 872.4
  Top Layer w8: U2.53@2145.67,1070.55 2178.84,1070.55 2245.85,1003.54 2245.85,564.24 2179.94,498.34 2179.94,358.21 P9.29@2230.71,307.44
PB15: P9.30 U2.54 | length 766.7
  Top Layer w8: U2.54@2145.67,1090.23 2181.01,1090.23 2264.44,1006.8 2264.44,535.42 2230.71,501.7 P9.30@2230.71,407.44
PC0: P6.20 U2.15 | length 1933
  Top Layer w8: P6.20@658.21,2144.36 658.21,1950.75 921.67,1687.29 921.67,1463.33 887.58,1429.24 887.58,1179.54 1080.92,986.2 1258.24,986.2 1340.46,1068.41 1340.46,1130.66 1437.82,1228.03 U2.15@1515.75,1228.03
PC1: P6.19 U2.16 | length 2092.5
  Top Layer w8: P6.19@658.21,2244.36 607.59,2193.74 607.59,1973.85 905.4,1676.03 905.4,1473.49 872.64,1440.73 872.64,1166.53 1066.07,973.11 1265.24,973.11 1355.45,1063.32 1355.45,1125.04 1438.75,1208.34 U2.16@1515.75,1208.34
PC2: P6.22 U2.17 | length 2005.5
  Top Layer w8: P6.22@558.21,2144.36 558.21,2000.21 887.12,1671.3 887.12,1484.81 854.57,1452.27 854.57,1166.22 1062.05,958.74 1271.94,958.74 1368.45,1055.25 1368.45,1115.56 1441.54,1188.66 U2.17@1515.75,1188.66
PC3: P6.21 U2.18 | length 2156.4
  Top Layer w8: P6.21@558.21,2244.36 511.79,2197.94 511.79,2020.44 868.03,1664.2 868.03,1495.46 840.03,1467.46 840.03,1162.38 1059.07,943.34 1276.87,943.34 1381.45,1047.92 1381.45,1109.67 1440.75,1168.97 U2.18@1515.75,1168.97
PC4: P9.11 U2.33 | length 1004.1
  Top Layer w8: P9.11@1330.71,307.44 1330.71,311.65 1281.22,361.14 1281.22,492.66 1361.31,572.75 1620.36,572.75 1732.28,684.67 U2.33@1732.28,952.44
PC5: P9.12 U2.34 | length 854.5
  Top Layer w8: P9.12@1330.71,407.44 1330.71,490.53 1397.14,556.96 1627.61,556.96 1751.97,681.32 U2.34@1751.97,952.44
PC10: P7.13 U2.78 | length 1170.3
  Top Layer w8: U2.78@2027.56,1582.36 2027.56,1614.12 2316.63,1903.18 2635.95,1903.18 2753.31,2020.54 2753.31,2194.46 P7.13@2803.21,2244.36
PC11: P7.16 U2.79 | length 1026.4
  Top Layer w8: U2.79@2007.87,1582.36 2007.87,1618.13 2318.02,1928.28 2619.19,1928.28 2703.21,2012.3 P7.16@2703.21,2144.36
PC12: P7.15 U2.80 | length 1100.3
  Top Layer w8: U2.80@1988.19,1582.36 1988.19,1618.14 2325.32,1955.26 2568,1955.26 2655.34,2042.61 2655.34,2196.49 P7.15@2703.21,2244.36
PC13: P6.15 PC13.1 U2.7 | length 1286.7
  Top Layer w8: P6.15@858.21,2244.36 809.17,2195.32 809.17,1895.94 1198.75,1506.36 1267.29,1506.36 1388.14,1385.51 U2.7@1515.75,1385.51
PC14: P6.18 R12.1 | length 789.8
  Top Layer w8: P6.18@758.21,2144.36 758.21,1912.59 979.81,1690.99 R12.1@979.81,1446.32
PC15: P6.17 R16.1 | length 1046.5
  Top Layer w8: P6.17@758.21,2244.36 708.99,2195.14 708.99,1930.47 939.77,1699.69 939.77,1379.8 962.92,1356.65 963.9,1356.65 978.21,1342.34 R16.1@978.21,1341.36 ; R16.1@988.21,1341.36 R16.1@988.21,1352.34
PD0: P7.18 U2.81 | length 938.9
  Top Layer w8: U2.81@1968.5,1582.36 1968.5,1619.28 2328.68,1979.47 2523.28,1979.47 2603.21,2059.4 P7.18@2603.21,2144.36
PD1: P7.17 U2.82 | length 1026.7
  Top Layer w8: U2.82@1948.82,1582.36 1948.82,1621.39 2327.01,1999.58 2486.93,1999.58 2552.56,2065.22 2552.56,2193.71 P7.17@2603.21,2244.36
PD2: P7.20 U2.83 | length 864.6
  Top Layer w8: U2.83@1929.13,1582.36 1929.13,1622.35 2328.39,2021.6 2439,2021.6 2503.21,2085.81 P7.20@2503.21,2144.36
PD3: P7.19 U2.84 | length 945.7
  Top Layer w8: U2.84@1909.45,1582.36 1909.45,1624.99 2326,2041.54 2390.53,2041.54 2451.93,2102.94 2451.93,2193.08 P7.19@2503.21,2244.36
PD4: P7.22 U2.85 | length 774.7
  Top Layer w8: U2.85@1889.76,1582.36 1889.76,1628.52 2403.21,2141.96 P7.22@2403.21,2144.36
PD5: P7.21 U2.86 | length 882.8
  Top Layer w8: U2.86@1870.08,1582.36 1870.08,1635.51 2358.63,2124.06 2358.63,2199.78 P7.21@2403.21,2244.36
PD6: P7.24 U2.87 | length 749.6
  Top Layer w8: U2.87@1850.39,1582.36 1850.39,1637.01 2303.21,2089.83 P7.24@2303.21,2144.36
PD7: P7.23 U2.88 | length 857.7
  Top Layer w8: U2.88@1830.71,1582.36 1830.71,1642.41 2256.98,2068.68 2256.98,2198.13 P7.23@2303.21,2244.36
PD8: P9.31 U2.55 | length 901.1
  Top Layer w8: U2.55@2145.67,1109.92 2183.18,1109.92 2285.04,1008.06 2285.04,353.11 P9.31@2330.71,307.44
PD9: P9.32 U2.56 | length 821.5
  Top Layer w8: U2.56@2145.67,1129.6 2184.38,1129.6 2330.71,983.27 P9.32@2330.71,407.44
PD10: P9.33 U2.57 | length 983.8
  Top Layer w8: U2.57@2145.67,1149.29 2186.4,1149.29 2384.8,950.89 2384.8,353.35 P9.33@2430.71,307.44
PD11: P9.34 U2.58 | length 904.5
  Top Layer w8: U2.58@2145.67,1168.97 2188.18,1168.97 2430.71,926.45 P9.34@2430.71,407.44
PD12: P9.35 U2.59 | length 1064.9
  Top Layer w8: U2.59@2145.67,1188.66 2186.88,1188.66 2482.5,893.04 2482.5,355.65 P9.35@2530.71,307.44
PD13: P9.36 U2.60 | length 984.7
  Top Layer w8: U2.60@2145.67,1208.34 2187.11,1208.34 2530.71,864.75 P9.36@2530.71,407.44
PD14: P9.37 U2.61 | length 1146.9
  Top Layer w8: U2.61@2145.67,1228.03 2189.06,1228.03 2583.87,833.22 2583.87,354.28 P9.37@2630.71,307.44
PD15: P9.38 U2.62 | length 1064.6
  Top Layer w8: U2.62@2145.67,1247.71 2189.26,1247.71 2630.71,806.26 P9.38@2630.71,409.52
PE0: P6.10 U2.97 | length 894.9
  Top Layer w8: P6.10@1158.21,2144.36 1158.21,1927.31 1211.8,1873.72 1429.88,1873.72 1653.54,1650.06 U2.97@1653.54,1582.36
PE1: P6.9 U2.98 | length 1041.6
  Top Layer w8: P6.9@1158.21,2244.36 1108.32,2194.47 1108.32,1930.09 1184.06,1854.35 1425.23,1854.35 1633.86,1645.72 U2.98@1633.86,1582.36
PE2: P6.12 U2.1 | length 947.7
  Top Layer w8: P6.12@1058.21,2144.36 1058.21,1880.38 1233.45,1705.14 1400.99,1705.14 1473.86,1632.27 1473.86,1512.51 1482.75,1503.62 U2.1@1515.75,1503.62
PE3: P6.11 U2.2 | length 1110.8
  Top Layer w8: P6.11@1058.21,2244.36 1008.52,2194.67 1008.52,1896.2 1214.88,1689.83 1386.22,1689.83 1456.55,1619.5 1456.55,1510.13 1482.75,1483.93 U2.2@1515.75,1483.93
PE4: P6.14 U2.3 | length 1040.6
  Top Layer w8: P6.14@958.21,2144.36 958.21,1915.51 1200.39,1673.33 1371.63,1673.33 1439.6,1605.36 1439.6,1490.53 1465.88,1464.25 U2.3@1515.75,1464.25
PE5: P6.13 U2.4 | length 1206.2
  Top Layer w8: P6.13@958.21,2244.36 911.64,2197.79 911.64,1930.08 1183.13,1658.59 1352.6,1658.59 1424.76,1586.43 1424.76,1471.34 1451.54,1444.56 U2.4@1515.75,1444.56
PE6: P6.16 U2.5 | length 1136.4
  Top Layer w8: P6.16@858.21,2144.36 858.21,1957.58 1172.29,1643.5 1345.3,1643.5 1404.28,1584.52 1404.28,1462.54 1441.94,1424.88 U2.5@1515.75,1424.88
PE7: P9.16 U2.38 | length 719.6
  Top Layer w8: P9.16@1530.71,407.44 1530.71,449.69 1565.66,484.64 1651.59,484.64 1830.71,663.76 U2.38@1830.71,952.44
PE8: P9.17 U2.39 | length 812.2
  Top Layer w8: P9.17@1630.71,307.44 1579.12,359.03 1579.12,444.37 1595.62,460.88 1652.8,460.88 1850.39,658.47 U2.39@1850.39,952.44
PE9: P9.18 U2.40 | length 644.1
  Top Layer w8: P9.18@1630.71,407.44 1870.08,646.81 U2.40@1870.08,952.44
PE10: P9.19 U2.41 | length 752.8
  Top Layer w8: P9.19@1730.71,307.44 1680.12,358.03 1680.12,431.09 1889.76,640.73 U2.41@1889.76,952.44
PE11: P9.20 U2.42 | length 619
  Top Layer w8: P9.20@1730.71,407.44 1730.71,453.77 1909.45,632.51 U2.42@1909.45,952.44
PE12: P9.21 U2.43 | length 725.2
  Top Layer w8: P9.21@1830.71,307.44 1783.07,355.08 1783.07,476.48 1929.13,622.55 U2.43@1929.13,952.44
PE13: P9.22 U2.44 | length 593.9
  Top Layer w8: P9.22@1830.71,407.44 1830.71,499 1948.82,617.11 U2.44@1948.82,952.44
PE14: P9.23 U2.45 | length 703.4
  Top Layer w8: P9.23@1930.71,307.44 1879.17,358.98 1879.17,518.96 1968.5,608.29 U2.45@1968.5,952.44
PE15: P9.24 U2.46 | length 568.8
  Top Layer w8: P9.24@1930.71,407.44 1930.71,536.72 1988.19,594.2 U2.46@1988.19,952.44
VBAT: C12.2 D2.1 P11.3 U2.6 | length 1844.3
  Top Layer w8: C12.2@1293.69,1585.69 1368.61,1510.77 ; C12.2@1293.9,1593.06 v2(1293.9,1613.38) ; C12.2@1296.53,1575.14 1368.61,1503.06 ; U2.6@1515.75,1405.19 1433.6,1405.19 ; 1368.61,1503.06 1368.61,1510.77 ; 1368.61,1503.06 1368.61,1463.66 1374.89,1457.38 ; 1368.61,1510.77 1374.89,1504.49 1374.89,1463.9 ; 1374.89,1457.38 1374.89,1463.9 ; 1374.89,1457.38 1427.08,1405.19 1433.6,1405.19 ; 1374.89,1463.9 1433.6,1405.19
  Top Layer w30: D2.1@699.12,1456.36 701.17,1456.36 702.51,1455.02 v2(702.51,1427.93) v2@702.51,1398.74 ; v2(702.05,1398.74) 702.68,1398.11 702.68,1066.89 P11.3@708.21,1061.36 ; C12.2@1292.04,1591.19 1293.9,1593.06 1314.22,1613.38 1325.05,1613.38 v2(1325.25,1613.58)
  Bottom Layer w30: v2(702.05,1398.74) v2@702.51,1399.19 ; 1277.35,1610.93 1322.6,1610.93 v2(1325.25,1613.58) ; v2@1322.36,1612.61 1321.6,1613.38 v2(1293.9,1613.38) 1072.4,1613.38 886.96,1427.93 731.25,1427.93 ; v2@702.51,1399.19 731.25,1427.93 ; v2@702.51,1399.19 v2(702.51,1427.93) 731.25,1427.93
VDD: C45.1 C46.1 C47.2 D2.2 P6.2 P6.4 P10.7 P10.8 P11.5 U2.11 U2.28 U2.75 | length 7023.3
  Top Layer w10: C46.1@1290.39,1251.48 1290.56,1251.66 1350.23,1251.66 1405.35,1306.77 ; v2@1312.64,1260.43 1348.08,1260.43 1394.42,1306.77 1405.35,1306.77 ; U2.11@1515.75,1306.77 1405.35,1306.77 ; v2(1621.21,850.36) 1633.86,863.01 U2.28@1633.86,952.44 ; U2.75@2145.67,1503.62 2177.91,1503.62 2200.82,1526.53 ; U2.75@2165.67,1504.12 2173.18,1511.63 2177.54,1511.63 2200.82,1534.91 ; C45.1@2204.3,1626.96 2200.82,1623.48 2200.82,1534.91 ; C45.1@2207.3,1629.96 2208.93,1628.32 2208.93,1534.64 2200.82,1526.53 ; 2200.82,1526.53 2200.82,1534.91
  Top Layer w30: v2(137.77,1110.02) 137.77,1093.41 ; v2(141.94,1150.3) 141.94,1097.58 137.77,1093.41 ; P10.8@357.21,636.36 P10.7@257.21,636.36 184.75,636.36 137.77,683.35 137.77,1093.41 ; v2(606.21,1323.05) 606.21,1355.52 v2(607.15,1356.45) ; D2.2@606.21,1456.36 606.87,1456.36 608.21,1455.02 608.21,1284.02 P11.5@608.21,1061.36 ; P6.4@1458.21,2144.36 P6.2@1558.21,2144.36 ; v2(1621.21,850.36) 1621.21,820.6 C47.2@1621.35,820.46 ; v2@2141.91,1629.96 C45.1@2207.3,1629.96 2204.3,1626.96 2172.19,1626.96 v2(2169.66,1624.43)
  Bottom Layer w30: P11.5@608.21,1061.36 P11.5@608.21,1065.07 ; v2(1312.64,1262.13) 1391.06,1262.13 1485.62,1356.69 1485.62,1439.81 ; 1405.67,1278.86 1400.72,1273.91 689.69,1273.91 640.55,1323.05 ; P6.2@1558.21,2144.36 1556.91,2143.06 1556.91,2084.36 1485.62,2013.07 1485.62,1517.02 ; v2(1621.21,850.36) 1567.09,850.36 1505.09,788.36 1202.98,788.36 844.2,1147.14 642.58,1147.14 ; 182.22,1110.02 563.26,1110.02 ; 182.22,1110.02 v2(137.77,1110.02) 137.77,1146.13 v2(141.94,1150.3) 182.22,1110.02 ; 563.26,1110.02 573.78,1099.5 P11.5@608.21,1065.07 ; 563.26,1110.02 584.29,1110.02 621.42,1147.14 642.58,1147.14 ; P11.5@608.21,1065.07 608.21,1112.77 642.58,1147.14 ; 640.55,1323.05 v2(607.15,1356.45) 607.15,1323.99 v2(606.21,1323.05) 640.55,1323.05 ; 1485.62,1439.81 1524.23,1478.42 ; 1485.62,1439.81 1485.62,1478.42 ; 1485.62,1478.42 1524.23,1478.42 ; 1485.62,1478.42 1485.62,1517.02 ; 1485.62,1517.02 1524.23,1478.42 ; 1524.23,1478.42 2098.62,1478.42 2169.66,1549.46 2169.66,1596.77 ; 2169.66,1596.77 2137.91,1628.52 v2(2141.91,1628.52) 2165.57,1628.52 v2(2169.66,1624.43) 2169.66,1596.77
VDDA: C13.1 R18.1 R19.2 U2.22 | length 1403.7
  Top Layer w8: C13.1@1402.03,927.4 1414.55,939.91 1444.25,969.62 1444.25,975.71 1444.25,979.56 1444.25,1065.63 1466.06,1087.44 1468.85,1090.23 ; C13.1@1413.06,941.4 1415.08,941.4 1415.08,949.89 1440.91,975.71 1440.91,1065.63 1440.91,1067.88 1441.45,1068.43 1463.26,1090.23 1468.85,1090.23 ; U2.22@1515.75,1090.23 1468.85,1090.23
  Top Layer w25: R18.1@675.15,689.26 R19.2@675.15,618.26 675.15,583.26 689.79,568.62 863.45,568.62 1106.8,811.96 1259.39,811.96 1369.33,921.9 1400.53,921.9 1402.03,923.4 C13.1@1402.03,927.4
VIO: C5.1 C42.2 P6.1 P6.3 P11.1 R19.1 S4.1 U2.50 U2.100 | length 7353.7
  Top Layer w8: U2.100@1594.49,1582.36 1594.49,1617.88 ; U2.50@2066.93,952.44 2066.93,903.82 ; C5.1@2097,820.88 2096.53,821.36 C5.1@2094.87,823.02 ; 1594.49,1617.88 1594.49,1627.88 1473.69,1748.68 C42.2@1439.49,1748.68 1446.26,1741.91 1470.47,1741.91 1594.49,1617.88 ; 2066.93,903.82 2066.93,894.85 2093.21,868.57 C5.1@2093.21,821.36 C5.1@2094.87,823.02 ; 2066.93,903.82 2100.73,870.02 2100.73,828.88 C5.1@2094.87,823.02
  Top Layer w22: v2(1430.95,1777.93) 1430.95,1776.31 1432.49,1774.77 1432.49,1755.68 C42.2@1439.49,1748.68
  Top Layer w30: v2(769.37,618.18) 735.85,618.18 R19.1@735.78,618.26 801.27,618.26 v2(802.15,619.14) ; v2(808.21,1621.36) v2(787.77,1600.92) 767.34,1580.49 767.34,1136.97 796.86,1107.44 796.86,1072.7 819.54,1050.02 855.6,1050.02 891.89,1013.74 891.89,793.91 ; v2@919.56,763.15 918.86,763.85 v2(891.89,763.85) 891.89,793.91 ; v2(922.56,763.23) 891.89,793.91 ; C5.1@2093.21,821.36 2096.53,821.36 2154.95,821.36 v2(2156.39,819.93) ; C5.1@2097,820.88 v2(2127.04,820.88) ; v3(2509.37,999.27) 2718.41,790.22 2718.41,625.31 2770.89,572.84 3323.07,572.84 3373.93,521.98 3373.93,245.33 3426.66,192.61 3511.47,192.61 S4.1@3512.71,191.36
  Bottom Layer w22: v2(808.21,1621.36) 878.92,1692.07 1377.15,1692.07 ; P6.3@1458.21,2244.36 1407.64,2193.79 1407.64,1801.25 1419.29,1789.59 ; 1377.15,1692.07 1398.94,1692.07 1430.95,1724.09 v2(1430.95,1777.93) 1419.29,1789.59 ; 1377.15,1692.07 1419.29,1734.22 1419.29,1789.59
  Bottom Layer w30: v2(787.77,1600.92) v2(808.21,1621.36) ; 826.86,675.67 802.15,650.96 ; P6.3@1458.21,2244.36 P6.1@1558.21,2244.36 ; v3(2509.37,999.27) 2335.73,999.27 v2(2156.39,819.93) ; 802.15,650.96 v2(769.37,618.18) 801.19,618.18 v2(802.15,619.14) 802.15,650.96 ; 802.15,650.96 884.36,733.17 ; 884.36,733.17 891.89,740.7 v2(891.89,763.85) v2@892.5,763.23 ; 884.36,733.17 922.56,733.17 ; v2@892.5,763.23 922.56,733.17 ; v2@892.5,763.23 v2(922.56,763.23) 922.56,733.17 ; 922.56,733.17 1030.78,624.95 2067.96,624.95 2127.04,684.03 2127.04,790.58 ; 2127.04,790.58 v2(2156.39,819.93) ; 2127.04,790.58 v2(2127.04,820.88) 2155.43,820.88 v2(2156.39,819.93)
VREF+: R18.2 U2.21 | length 991.5
  Top Layer w8: R18.2@735.78,689.26 934.42,689.26 1094.45,849.28 1254.09,849.28 1425.59,1020.78 1425.59,1084.5 1451.01,1109.92 U2.21@1515.75,1109.92
VREF-: R17.2 U2.20 | length 994.7
  Top Layer w8: R17.2@735.78,760.26 765.99,760.26 798,728.24 939.7,728.24 1082.06,870.6 1253.37,870.6 1412.16,1029.4 1412.16,1089.45 1452.31,1129.6 U2.20@1515.75,1129.6
X32KI: C9.2 R12.2 U2.8 Y2.1 | length 491
  Top Layer w8: R12.2@1038.84,1444.36 1041.84,1441.36 Y2.1@1138.21,1441.36 ; Y2.1@1158.21,1441.36 1252.95,1441.36 1276.4,1417.9 1276.4,1416.61 1289.51,1403.5 1290.8,1403.5 1290.8,1402.21 1304.4,1388.61 1305.7,1388.61 1328.48,1365.82 U2.8@1515.75,1365.82
X32KO: C10.2 R16.2 U2.9 Y2.2 | length 517.8
  Top Layer w8: R16.2@1038.84,1341.36 1040.41,1342.93 Y2.2@1138.21,1342.93 1186.25,1294.89 1281.61,1294.89 1290.4,1303.68 C10.2@1290.4,1333.23 ; C10.2@1303.31,1346.14 U2.9@1515.75,1346.14
XI: C7.2 U2.12 Y1.1 | length 542.7
  Top Layer w8: Y1.1@1063.21,1190.91 1063.21,1186.97 1102.83,1147.36 1269.09,1147.36 1288.36,1166.62 1288.36,1187.07 1295.19,1193.89 1326.63,1193.89 1419.82,1287.08 U2.12@1515.75,1287.08
XO: C8.2 U2.13 Y1.3 | length 513.7
  Top Layer w8: Y1.3@1138.01,1100.36 1138.01,1096.42 1155.67,1078.77 1159.6,1078.77 1175.11,1063.26 1282.95,1063.26 1290.4,1070.7 C8.2@1290.4,1099.73 1293.9,1103.23 1293.9,1131.75 1429.55,1267.4 U2.13@1515.75,1267.4
pads on no net: P2. P2.7 P14.A8 P14.B8 P15.A8 P15.B8 S1.0 S1.3 U1. U2.0

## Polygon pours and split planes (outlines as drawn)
GND on Top Layer "GND" (hatched Horizontal grid 8 track 8, remove dead copper, pour order 0): 0,3267.72 0,0 3661.42,0 3661.42,3267.72
GND on Bottom Layer "GND" (hatched Horizontal grid 8 track 8, remove dead copper, pour order 1): 0,3267.72 0,0 3661.42,0 3661.42,3267.72

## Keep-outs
Keep-Out Layer:
  the board outline again, w10

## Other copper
Top Layer:
  region net GND: 229.6,3255.14 12.2,3255.14 12.2,2948.41 229.6,2948.41
  rectangle net GND: 3429.39,2948.41 3649.22,3255.14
